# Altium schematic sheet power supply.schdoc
size 235 x 107 mm
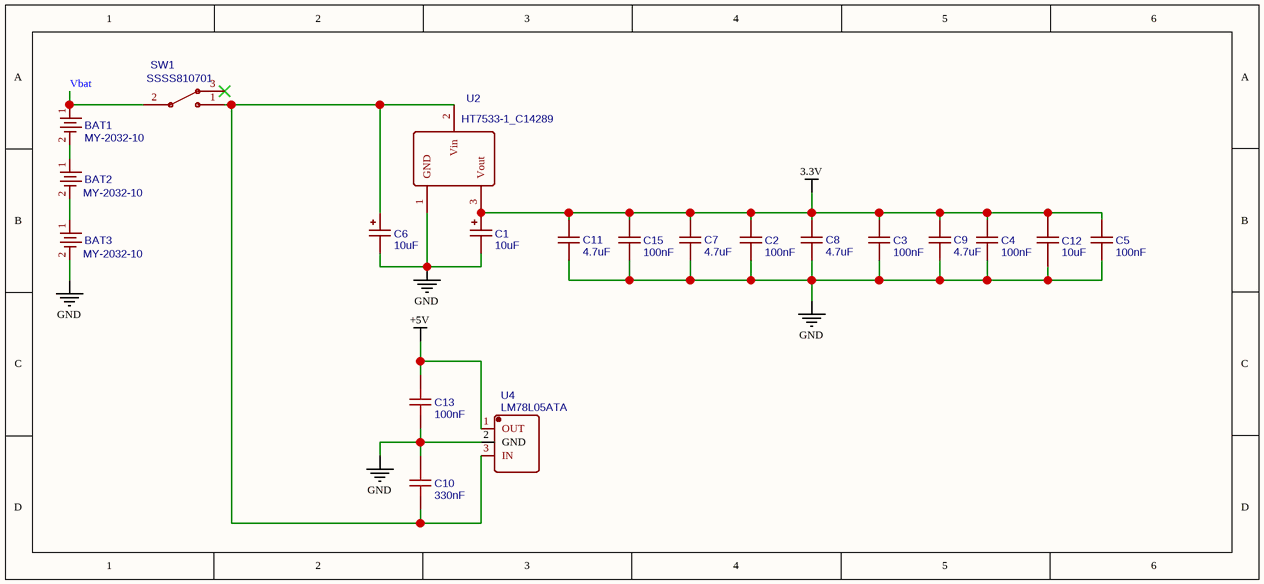
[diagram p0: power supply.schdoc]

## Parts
BAT1  MY-2032-10  [BATTERY-SMD-MY-2032]
BAT2  MY-2032-10  [BATTERY-SMD-MY-2032]
BAT3  MY-2032-10  [BATTERY-SMD-MY-2032]
C1  10uF  [CAP-SMD_L3.2-W1.6-RD-C7171]
C2  100nF  [C1206]
C3  100nF  [C1206]
C4  100nF  [C1206]
C5  100nF  [C1206]
C6  10uF  [CAP-SMD_L3.2-W1.6-RD-C7171]
C7  4.7uF  [C1206]
C8  4.7uF  [C1206]
C9  4.7uF  [C1206]
C10  330nF  [C0603]
C11  4.7uF  [C1206]
C12  10uF  [C0603]
C13  100nF  [C0603]
C15  100nF  [C1206]
SW1  SSSS810701  [SW-SMD_SSSS810701]
U2  HT7533-1_C14289  [SOT-89-3_L4.5-W2.5-P1.50-LS4.2-BR]
U4  LM78L05ATA  [TO-92-3_L4.9-W3.7-P1.27-L]

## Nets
3.3V: C1.1 C2.2 C3.2 C4.2 C5.2 C7.1 C8.1 C9.1 C11.1 C12.2 C15.2 U2.3(Vout)
+5V: C13.2 U4.1(OUT)
GND: BAT3.2(BAT-) C1.2 C2.1 C3.1 C4.1 C5.1 C6.2 C7.2 C8.2 C9.2 C10.2 C11.2 C12.1 C13.1 C15.1 U2.1(GND) U4.2(GND)
Vbat: BAT1.1(BAT+) SW1.2
NetBAT1_2: BAT1.2(BAT-) BAT2.1(BAT+)
NetBAT2_2: BAT2.2(BAT-) BAT3.1(BAT+)
NetC6_1: C6.1 C10.1 SW1.1 U2.2(Vin) U4.3(IN)

Not connected (* = marked no-connect by the designer): SW1 3*

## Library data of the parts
BAT1-BAT3 = MY-2032-10: Manufacturer: MYOUNG(美阳); Contributor: lcsc
C1 C6 = 10uF: Manufacturer: Kyocera AVX; Manufacturer Part: TAJA106K016RNJ; nameAlias: Value
C2-C5 C15 = 100nF: Manufacturer Part: CL31B104KBCNNNC; Manufacturer: SAMSUNG(三星); nameAlias: Value
C7-C9 C11 = 4.7uF: Manufacturer: FH(风华); Manufacturer Part: 1206B475K500NT; nameAlias: Value
C10 = 330nF: Manufacturer: TDK; Manufacturer Part: CGA3E3X7R1H334KT000N; nameAlias: Value; Contributor: LCSC
C12 = 10uF: Manufacturer: SAMSUNG(三星); Manufacturer Part: CL10A106MA8NRNC; nameAlias: Value
C13 = 100nF: Manufacturer: FH(风华); Manufacturer Part: 0603B104M250NT; nameAlias: Value; Contributor: LCSC
SW1 = SSSS810701: Manufacturer: ALPSALPINE(阿尔卑斯阿尔派); Contributor: LCSC
U2 = HT7533-1_C14289: Manufacturer: HOLTEK(合泰/盛群)
U4 = LM78L05ATA: Manufacturer: HTC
